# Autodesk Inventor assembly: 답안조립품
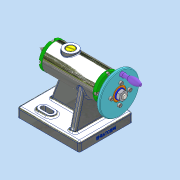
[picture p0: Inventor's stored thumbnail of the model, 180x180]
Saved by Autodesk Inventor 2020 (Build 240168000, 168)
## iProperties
Created: 2021-11
Part Number: 답안조립품
Document SubType Name: Assembly
Designer: user
Author: user
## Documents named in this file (18)
- C:\Users\user\Desktop\711112V1008 (1)\답안조립품.iam
- C:\Users\user\Desktop\711112V1008 (1)\나사.ipt
- C:\Users\user\Desktop\711112V1008 (1)\나사축.ipt
- C:\Users\user\Desktop\711112V1008 (1)\너트 M8.ipt
- C:\Users\user\Desktop\711112V1008 (1)\돌림판.ipt
- C:\Users\user\Desktop\711112V1008 (1)\멈춤나사 M3.ipt
- C:\Users\user\Desktop\711112V1008 (1)\본체.ipt
- C:\Users\user\Desktop\711112V1008 (1)\볼트 M3.ipt
- C:\Users\user\Desktop\711112V1008 (1)\부시.ipt
- C:\Users\user\Desktop\711112V1008 (1)\센터.ipt
- C:\Users\user\Desktop\711112V1008 (1)\센터홀더.ipt
- C:\Users\user\Desktop\711112V1008 (1)\슬리브.ipt
- C:\Users\user\Desktop\711112V1008 (1)\와셔.ipt
- C:\Users\user\Desktop\711112V1008 (1)\중공축.ipt
- C:\Users\user\Desktop\711112V1008 (1)\커버.ipt
- C:\Users\user\Desktop\711112V1008 (1)\키 4 x 4 x 10.ipt
- C:\Users\user\Desktop\711112V1008 (1)\플랜지.ipt
- C:\Users\user\Desktop\711112V1008 (1)\핸들.ipt
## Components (2 placed, 2 different names)
1. 플랜지:1
2. 핸들:1 — 플러쉬:4
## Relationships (1: Flush 1)
- 플러쉬:4 [Flush]: 핸들:1
